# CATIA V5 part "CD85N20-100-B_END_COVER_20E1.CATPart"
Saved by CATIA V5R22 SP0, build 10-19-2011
Part number: CD85N20-100-B_END_COVER_20E1
Revision: ANY
Definition: UNKNOWN
Nomenclature: CD85N20-100-B_END_COVER_20E1
Source: Unknown
Bounding box of the stored display mesh (mm): x -12 to 12, y -12 to 12, z 0 to 35
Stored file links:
  D:\PER\CAO_PER_MODIF_2025\CAO_PER_pick&place_2024P\Sous_Ensemble_Flacon\CD85N20-100-B_END_COVER_20E1.CATPart
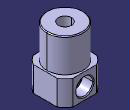
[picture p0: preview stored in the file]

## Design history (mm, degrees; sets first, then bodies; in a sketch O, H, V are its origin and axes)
Body1 "Chamfer1" (main body)
  Solid1: solid without history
